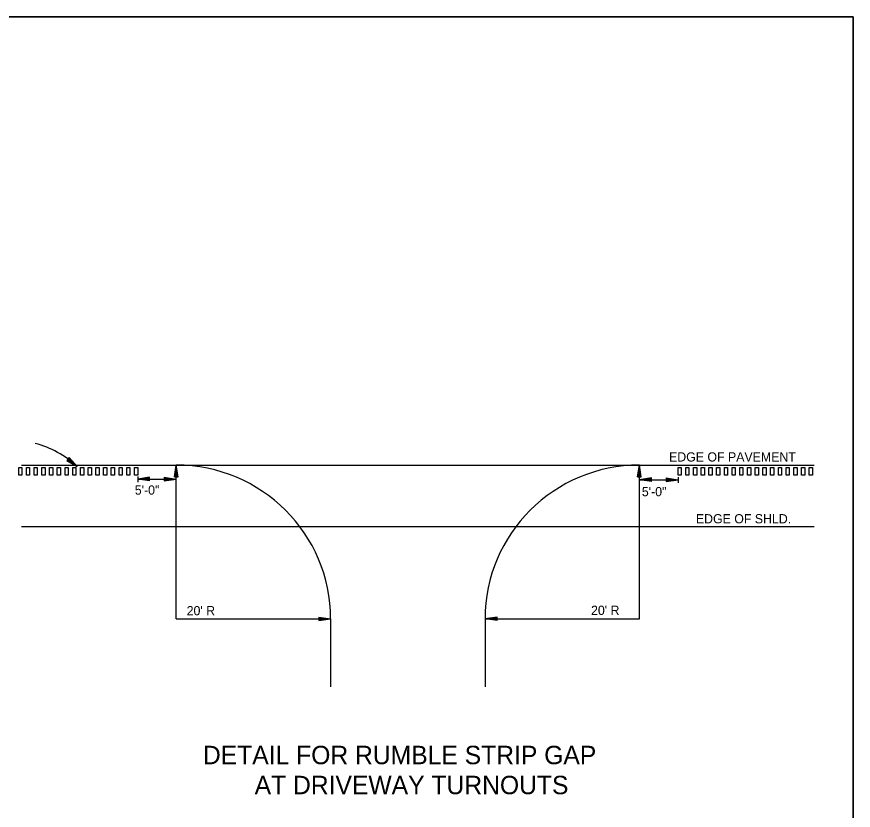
# Model space of a CAD drawing. Extents: x 8229 to 8749, y 14916 to 18021.
# Drawn here: x 8571.4 to 8749, y 15520.3 to 15688.8 of the extents above; entities that cross this region are included whole.
import ezdxf

# ---------------------------------------------------------------- set-up
doc = ezdxf.new("R2010")
doc.units = 0
for name, color, linetype in [('Default', 7, 'Continuous'), ('DSN_DRFT_Junk-No-Plot', 7, 'Continuous'), ('R_Dimension', 7, 'Continuous'), ('R_Draft', 7, 'Continuous')]:
    doc.layers.add(name, color=color, linetype=linetype)

msp = doc.modelspace()

# ---------------------------------------------------------------- linework, layer by layer
at = {"layer": 'Default'}
msp.add_lwpolyline([(8748.98, 15353.52), (8748.98, 15688.81), (8230.82, 15688.81), (8230.82, 15353.52)], close=True, dxfattribs=at)
at = {"layer": 'DSN_DRFT_Junk-No-Plot'}
msp.add_lwpolyline([(8230.82, 15688.81), (8748.98, 15688.81), (8748.98, 15353.52), (8230.82, 15353.52)], close=True, dxfattribs=at)
at = {"layer": 'R_Dimension'}
for p, q in [((8582.49, 15595.21), (8582, 15594.63)), ((8582.17, 15594.82), (8582.88, 15594.39)), ((8582.21, 15594.87), (8582.55, 15594.66)), ((8582.28, 15594.96), (8582.55, 15594.66)), ((8582.32, 15595.01), (8582.88, 15594.39)), ((8582.37, 15595.06), (8583.21, 15594.11)), ((8582.41, 15595.11), (8583.53, 15593.84)), ((8582.45, 15595.16), (8583.86, 15593.56)), ((8582.49, 15595.21), (8584.19, 15593.29)), ((8582, 15594.63), (8584.19, 15593.29)), ((8582.04, 15594.67), (8583.86, 15593.56)), ((8582.08, 15594.72), (8583.53, 15593.84)), ((8582.12, 15594.77), (8583.21, 15594.11)), ((8604.86, 15591.1), (8605.24, 15593.62)), ((8604.86, 15591.1), (8605.24, 15593.62)), ((8604.92, 15591.1), (8605.24, 15593.2)), ((8604.92, 15591.1), (8605.24, 15593.2)), ((8605.62, 15591.1), (8605.24, 15593.62)), ((8605.62, 15591.1), (8605.24, 15593.62)), ((8605.56, 15591.1), (8605.24, 15593.2)), ((8605.56, 15591.1), (8605.24, 15593.2)), ((8703.2, 15591.1), (8703.58, 15593.62)), ((8703.2, 15591.1), (8703.58, 15593.62)), ((8703.27, 15591.1), (8703.58, 15593.2)), ((8703.27, 15591.1), (8703.58, 15593.2)), ((8703.96, 15591.1), (8703.58, 15593.62)), ((8703.96, 15591.1), (8703.58, 15593.62)), ((8703.9, 15591.1), (8703.58, 15593.2)), ((8703.9, 15591.1), (8703.58, 15593.2)), ((8604.99, 15591.1), (8605.24, 15592.77)), ((8604.99, 15591.1), (8605.24, 15592.77)), ((8605.05, 15591.1), (8605.24, 15592.34)), ((8605.05, 15591.1), (8605.24, 15592.34)), ((8605.12, 15591.1), (8605.24, 15591.92)), ((8605.12, 15591.1), (8605.24, 15591.92)), ((8605.18, 15591.1), (8605.24, 15591.49)), ((8605.18, 15591.1), (8605.24, 15591.49)), ((8605.49, 15591.1), (8605.24, 15592.77)), ((8605.49, 15591.1), (8605.24, 15592.77)), ((8605.43, 15591.1), (8605.24, 15592.34)), ((8605.43, 15591.1), (8605.24, 15592.34)), ((8605.37, 15591.1), (8605.24, 15591.92)), ((8605.37, 15591.1), (8605.24, 15591.92)), ((8605.3, 15591.1), (8605.24, 15591.49)), ((8605.3, 15591.1), (8605.24, 15591.49)), ((8703.33, 15591.1), (8703.58, 15592.77)), ((8703.33, 15591.1), (8703.58, 15592.77)), ((8703.39, 15591.1), (8703.58, 15592.34)), ((8703.39, 15591.1), (8703.58, 15592.34)), ((8703.46, 15591.1), (8703.58, 15591.92)), ((8703.46, 15591.1), (8703.58, 15591.92)), ((8703.52, 15591.1), (8703.58, 15591.49)), ((8703.52, 15591.1), (8703.58, 15591.49)), ((8703.84, 15591.1), (8703.58, 15592.77)), ((8703.84, 15591.1), (8703.58, 15592.77)), ((8703.77, 15591.1), (8703.58, 15592.34)), ((8703.77, 15591.1), (8703.58, 15592.34)), ((8703.71, 15591.1), (8703.58, 15591.92)), ((8703.71, 15591.1), (8703.58, 15591.92)), ((8703.64, 15591.1), (8703.58, 15591.49)), ((8703.64, 15591.1), (8703.58, 15591.49)), ((8599.59, 15591.04), (8597.05, 15590.66)), ((8599.59, 15590.28), (8597.05, 15590.66)), ((8599.59, 15590.97), (8597.47, 15590.66)), ((8599.59, 15590.34), (8597.47, 15590.66)), ((8599.59, 15590.91), (8597.91, 15590.66)), ((8599.59, 15590.41), (8597.91, 15590.66)), ((8599.59, 15590.85), (8598.33, 15590.66)), ((8599.59, 15590.47), (8598.33, 15590.66)), ((8599.59, 15590.78), (8598.76, 15590.66)), ((8599.59, 15590.53), (8598.76, 15590.66)), ((8599.59, 15590.72), (8599.19, 15590.66)), ((8599.59, 15590.6), (8599.19, 15590.66)), ((8599.59, 15590.28), (8599.59, 15591.04)), ((8602.7, 15591.04), (8605.24, 15590.66)), ((8602.7, 15591.04), (8602.7, 15590.28)), ((8602.7, 15590.97), (8604.82, 15590.66)), ((8602.7, 15590.91), (8604.38, 15590.66)), ((8602.7, 15590.85), (8603.96, 15590.66)), ((8602.7, 15590.78), (8603.53, 15590.66)), ((8602.7, 15590.72), (8603.1, 15590.66)), ((8602.7, 15590.28), (8605.24, 15590.66)), ((8602.7, 15590.53), (8603.53, 15590.66)), ((8602.7, 15590.41), (8604.38, 15590.66)), ((8602.7, 15590.34), (8604.82, 15590.66)), ((8602.7, 15590.47), (8603.96, 15590.66)), ((8602.7, 15590.6), (8603.1, 15590.66)), ((8604.86, 15591.1), (8605.62, 15591.1)), ((8604.86, 15591.1), (8605.62, 15591.1)), ((8703.2, 15591.1), (8703.96, 15591.1)), ((8703.2, 15591.1), (8703.96, 15591.1)), ((8706.12, 15590.89), (8703.58, 15590.51)), ((8706.12, 15590.13), (8703.58, 15590.51)), ((8706.12, 15590.82), (8704.01, 15590.51)), ((8706.12, 15590.19), (8704.01, 15590.51)), ((8706.12, 15590.76), (8704.44, 15590.51)), ((8706.12, 15590.26), (8704.44, 15590.51)), ((8706.12, 15590.7), (8704.87, 15590.51)), ((8706.12, 15590.32), (8704.87, 15590.51)), ((8706.12, 15590.63), (8705.3, 15590.51)), ((8706.12, 15590.39), (8705.3, 15590.51)), ((8706.12, 15590.57), (8705.72, 15590.51)), ((8706.12, 15590.45), (8705.72, 15590.51)), ((8706.12, 15590.13), (8706.12, 15590.89)), ((8709.24, 15590.89), (8711.78, 15590.51)), ((8709.24, 15590.89), (8709.24, 15590.13)), ((8709.24, 15590.82), (8711.35, 15590.51)), ((8709.24, 15590.76), (8710.92, 15590.51)), ((8709.24, 15590.7), (8710.49, 15590.51)), ((8709.24, 15590.63), (8710.06, 15590.51)), ((8709.24, 15590.57), (8709.64, 15590.51)), ((8709.24, 15590.13), (8711.78, 15590.51)), ((8709.24, 15590.38), (8710.06, 15590.51)), ((8709.24, 15590.26), (8710.92, 15590.51)), ((8709.24, 15590.19), (8711.35, 15590.51)), ((8709.24, 15590.32), (8710.49, 15590.51)), ((8709.24, 15590.45), (8709.64, 15590.51)), ((8635.48, 15561.36), (8638.02, 15560.98)), ((8635.48, 15561.36), (8635.48, 15560.6)), ((8635.48, 15561.36), (8638.02, 15560.98)), ((8635.48, 15561.36), (8635.48, 15560.6)), ((8635.48, 15561.3), (8637.6, 15560.98)), ((8635.48, 15561.3), (8637.6, 15560.98)), ((8635.48, 15561.23), (8637.16, 15560.98)), ((8635.48, 15561.23), (8637.16, 15560.98)), ((8635.48, 15561.17), (8636.74, 15560.98)), ((8635.48, 15561.17), (8636.74, 15560.98)), ((8635.48, 15561.1), (8636.31, 15560.98)), ((8635.48, 15561.1), (8636.31, 15560.98)), ((8673.34, 15561.36), (8670.8, 15560.98)), ((8673.34, 15561.36), (8670.8, 15560.98)), ((8673.34, 15561.3), (8671.23, 15560.98)), ((8673.34, 15561.3), (8671.23, 15560.98)), ((8673.34, 15561.23), (8671.66, 15560.98)), ((8673.34, 15561.23), (8671.66, 15560.98)), ((8673.34, 15561.17), (8672.09, 15560.98)), ((8673.34, 15561.17), (8672.09, 15560.98)), ((8673.34, 15561.11), (8672.52, 15560.98)), ((8673.34, 15561.11), (8672.52, 15560.98)), ((8673.34, 15560.6), (8673.34, 15561.36)), ((8673.34, 15560.6), (8673.34, 15561.36)), ((8635.48, 15561.04), (8635.89, 15560.98)), ((8635.48, 15561.04), (8635.89, 15560.98)), ((8635.48, 15560.6), (8638.02, 15560.98)), ((8635.48, 15560.86), (8636.31, 15560.98)), ((8635.48, 15560.73), (8637.16, 15560.98)), ((8635.48, 15560.67), (8637.6, 15560.98)), ((8635.48, 15560.79), (8636.74, 15560.98)), ((8635.48, 15560.92), (8635.89, 15560.98)), ((8635.48, 15560.6), (8638.02, 15560.98)), ((8635.48, 15560.86), (8636.31, 15560.98)), ((8635.48, 15560.73), (8637.16, 15560.98)), ((8635.48, 15560.67), (8637.6, 15560.98)), ((8635.48, 15560.79), (8636.74, 15560.98)), ((8635.48, 15560.92), (8635.89, 15560.98)), ((8673.34, 15560.6), (8670.8, 15560.98)), ((8673.34, 15560.6), (8670.8, 15560.98)), ((8673.34, 15560.67), (8671.23, 15560.98)), ((8673.34, 15560.67), (8671.23, 15560.98)), ((8673.34, 15560.73), (8671.66, 15560.98)), ((8673.34, 15560.73), (8671.66, 15560.98)), ((8673.34, 15560.79), (8672.09, 15560.98)), ((8673.34, 15560.79), (8672.09, 15560.98)), ((8673.34, 15560.86), (8672.52, 15560.98)), ((8673.34, 15560.86), (8672.52, 15560.98)), ((8673.34, 15561.04), (8672.94, 15560.98)), ((8673.34, 15561.04), (8672.94, 15560.98)), ((8673.34, 15560.92), (8672.94, 15560.98)), ((8673.34, 15560.92), (8672.94, 15560.98))]:
    msp.add_line(p, q, dxfattribs=at)
at = {"layer": 'R_Draft'}
for p, q in [((8572.41, 15593.62), (8740.68, 15593.62)), ((8605.24, 15560.98), (8605.24, 15593.62)), ((8703.58, 15560.98), (8703.58, 15593.62)), ((8597.05, 15591.22), (8597.05, 15590.01)), ((8597.05, 15590.66), (8605.24, 15590.66)), ((8703.58, 15590.51), (8711.78, 15590.51)), ((8711.78, 15591.07), (8711.78, 15589.86)), ((8572.41, 15580.57), (8740.68, 15580.57)), ((8605.24, 15560.98), (8638.02, 15560.98)), ((8638.02, 15560.98), (8638.02, 15546.53)), ((8670.8, 15560.98), (8670.8, 15546.53)), ((8670.8, 15560.98), (8703.58, 15560.98))]:
    msp.add_line(p, q, dxfattribs=at)
for points in [[(8571.78, 15591.45), (8571.78, 15593.08), (8572.47, 15593.08), (8572.47, 15591.45), (8571.78, 15591.45)], [(8573.42, 15591.45), (8573.42, 15593.08), (8574.1, 15593.08), (8574.1, 15591.45), (8573.42, 15591.45)], [(8575.06, 15591.45), (8575.06, 15593.08), (8575.74, 15593.08), (8575.74, 15591.45), (8575.06, 15591.45)], [(8576.7, 15591.45), (8576.7, 15593.08), (8577.38, 15593.08), (8577.38, 15591.45), (8576.7, 15591.45)], [(8578.34, 15591.45), (8578.34, 15593.08), (8579.02, 15593.08), (8579.02, 15591.45), (8578.34, 15591.45)], [(8579.98, 15591.45), (8579.98, 15593.08), (8580.66, 15593.08), (8580.66, 15591.45), (8579.98, 15591.45)], [(8581.62, 15591.45), (8581.62, 15593.08), (8582.3, 15593.08), (8582.3, 15591.45), (8581.62, 15591.45)], [(8583.25, 15591.45), (8583.25, 15593.08), (8583.94, 15593.08), (8583.94, 15591.45), (8583.25, 15591.45)], [(8584.89, 15591.45), (8584.89, 15593.08), (8585.58, 15593.08), (8585.58, 15591.45), (8584.89, 15591.45)], [(8586.53, 15591.45), (8586.53, 15593.08), (8587.22, 15593.08), (8587.22, 15591.45), (8586.53, 15591.45)], [(8588.17, 15591.45), (8588.17, 15593.08), (8588.85, 15593.08), (8588.85, 15591.45), (8588.17, 15591.45)], [(8589.81, 15591.45), (8589.81, 15593.08), (8590.49, 15593.08), (8590.49, 15591.45), (8589.81, 15591.45)], [(8591.45, 15591.45), (8591.45, 15593.08), (8592.13, 15593.08), (8592.13, 15591.45), (8591.45, 15591.45)], [(8593.09, 15591.45), (8593.09, 15593.08), (8593.77, 15593.08), (8593.77, 15591.45), (8593.09, 15591.45)], [(8594.73, 15591.45), (8594.73, 15593.08), (8595.41, 15593.08), (8595.41, 15591.45), (8594.73, 15591.45)], [(8596.37, 15591.45), (8596.37, 15593.08), (8597.05, 15593.08), (8597.05, 15591.45), (8596.37, 15591.45)], [(8711.78, 15591.45), (8711.78, 15593.08), (8712.46, 15593.08), (8712.46, 15591.45), (8711.78, 15591.45)], [(8713.42, 15591.45), (8713.42, 15593.08), (8714.1, 15593.08), (8714.1, 15591.45), (8713.42, 15591.45)], [(8715.06, 15591.45), (8715.06, 15593.08), (8715.74, 15593.08), (8715.74, 15591.45), (8715.06, 15591.45)], [(8716.69, 15591.45), (8716.69, 15593.08), (8717.38, 15593.08), (8717.38, 15591.45), (8716.69, 15591.45)], [(8718.33, 15591.45), (8718.33, 15593.08), (8719.02, 15593.08), (8719.02, 15591.45), (8718.33, 15591.45)], [(8719.97, 15591.45), (8719.97, 15593.08), (8720.65, 15593.08), (8720.65, 15591.45), (8719.97, 15591.45)], [(8721.61, 15591.45), (8721.61, 15593.08), (8722.29, 15593.08), (8722.29, 15591.45), (8721.61, 15591.45)], [(8723.25, 15591.45), (8723.25, 15593.08), (8723.93, 15593.08), (8723.93, 15591.45), (8723.25, 15591.45)], [(8724.89, 15591.45), (8724.89, 15593.08), (8725.57, 15593.08), (8725.57, 15591.45), (8724.89, 15591.45)], [(8726.53, 15591.45), (8726.53, 15593.08), (8727.21, 15593.08), (8727.21, 15591.45), (8726.53, 15591.45)], [(8728.17, 15591.45), (8728.17, 15593.08), (8728.85, 15593.08), (8728.85, 15591.45), (8728.17, 15591.45)], [(8729.81, 15591.45), (8729.81, 15593.08), (8730.49, 15593.08), (8730.49, 15591.45), (8729.81, 15591.45)], [(8731.44, 15591.45), (8731.44, 15593.08), (8732.13, 15593.08), (8732.13, 15591.45), (8731.44, 15591.45)], [(8733.08, 15591.45), (8733.08, 15593.08), (8733.77, 15593.08), (8733.77, 15591.45), (8733.08, 15591.45)], [(8734.72, 15591.45), (8734.72, 15593.08), (8735.4, 15593.08), (8735.4, 15591.45), (8734.72, 15591.45)], [(8736.36, 15591.45), (8736.36, 15593.08), (8737.04, 15593.08), (8737.04, 15591.45), (8736.36, 15591.45)], [(8738, 15591.45), (8738, 15593.08), (8738.68, 15593.08), (8738.68, 15591.45), (8738, 15591.45)], [(8739.64, 15591.45), (8739.64, 15593.08), (8740.32, 15593.08), (8740.32, 15591.45), (8739.64, 15591.45)]]:
    msp.add_lwpolyline(points, dxfattribs=at)
for centre, major_axis, start_param, end_param in [((8570.08, 15578.5), (20.49, 0), 0.810903, 1.313859), ((8605.24, 15560.98), (-32.78, 0), 3.141593, 4.712389), ((8703.58, 15560.98), (-32.78, 0), 4.712389, 6.283185)]:
    msp.add_ellipse(centre, major_axis=major_axis, ratio=0.995751, start_param=start_param, end_param=end_param, dxfattribs=at)

# ---------------------------------------------------------------- texts
for s, height, p in [('EDGE OF PAVEMENT', 1.9582, (8709.87, 15594.38)), ('5\'-0"', 1.958, (8596.44, 15587.35)), ('5\'-0"', 1.958, (8704.1, 15587.01)), ('EDGE OF SHLD.', 1.9582, (8715.57, 15581.25)), ("20' R", 1.958, (8607.45, 15561.74)), ("20' R", 1.958, (8693.31, 15561.82)), ('DETAIL FOR RUMBLE STRIP GAP', 3.9164, (8610.9, 15530.12)), ('AT DRIVEWAY TURNOUTS', 3.9164, (8621.88, 15523.75))]:
    msp.add_text(s, height=height, dxfattribs=at).set_placement(p)

doc.saveas('drawing.dxf')
